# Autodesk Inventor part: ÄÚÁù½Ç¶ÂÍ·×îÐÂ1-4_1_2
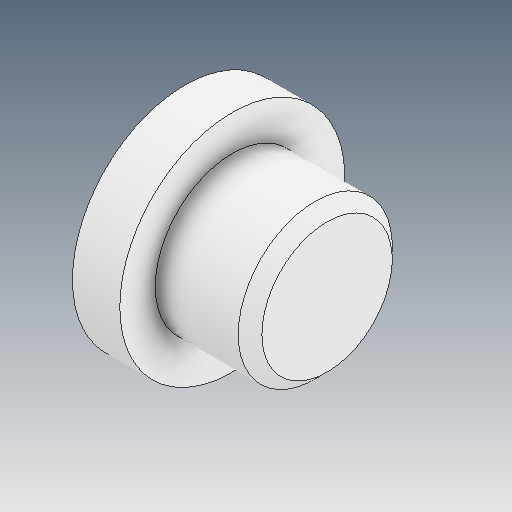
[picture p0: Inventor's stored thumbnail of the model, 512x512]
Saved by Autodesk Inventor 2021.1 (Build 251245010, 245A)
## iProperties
Created: 2021-05
Part Number: ÄÚÁù½Ç¶ÂÍ·×îÐÂ1-4_1_2
Material: Ogólny
Document SubType Name: Modeling
Designer: user
Density: 1 g/cm^3
Appearance: Domyślna
Author: user
Revision Number: ÈÎºÎ
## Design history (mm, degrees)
feature "ÊäÈë1"
node "Bryła1"
